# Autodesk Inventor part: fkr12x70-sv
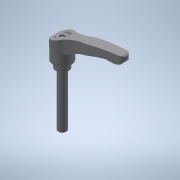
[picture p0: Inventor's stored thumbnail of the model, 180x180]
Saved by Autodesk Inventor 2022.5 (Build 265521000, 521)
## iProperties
Created: 2016-12
Part Number: fkr12x70-sv
Material: 一般
Document SubType Name: Modeling
Designer: imaocorp
Density: 1 g/cm^3
Appearance: 既定
Author: imaocorp
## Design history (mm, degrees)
node "fkr12x70-sv.x_t1"
node "K1000_412080_012"
node "Base1"
